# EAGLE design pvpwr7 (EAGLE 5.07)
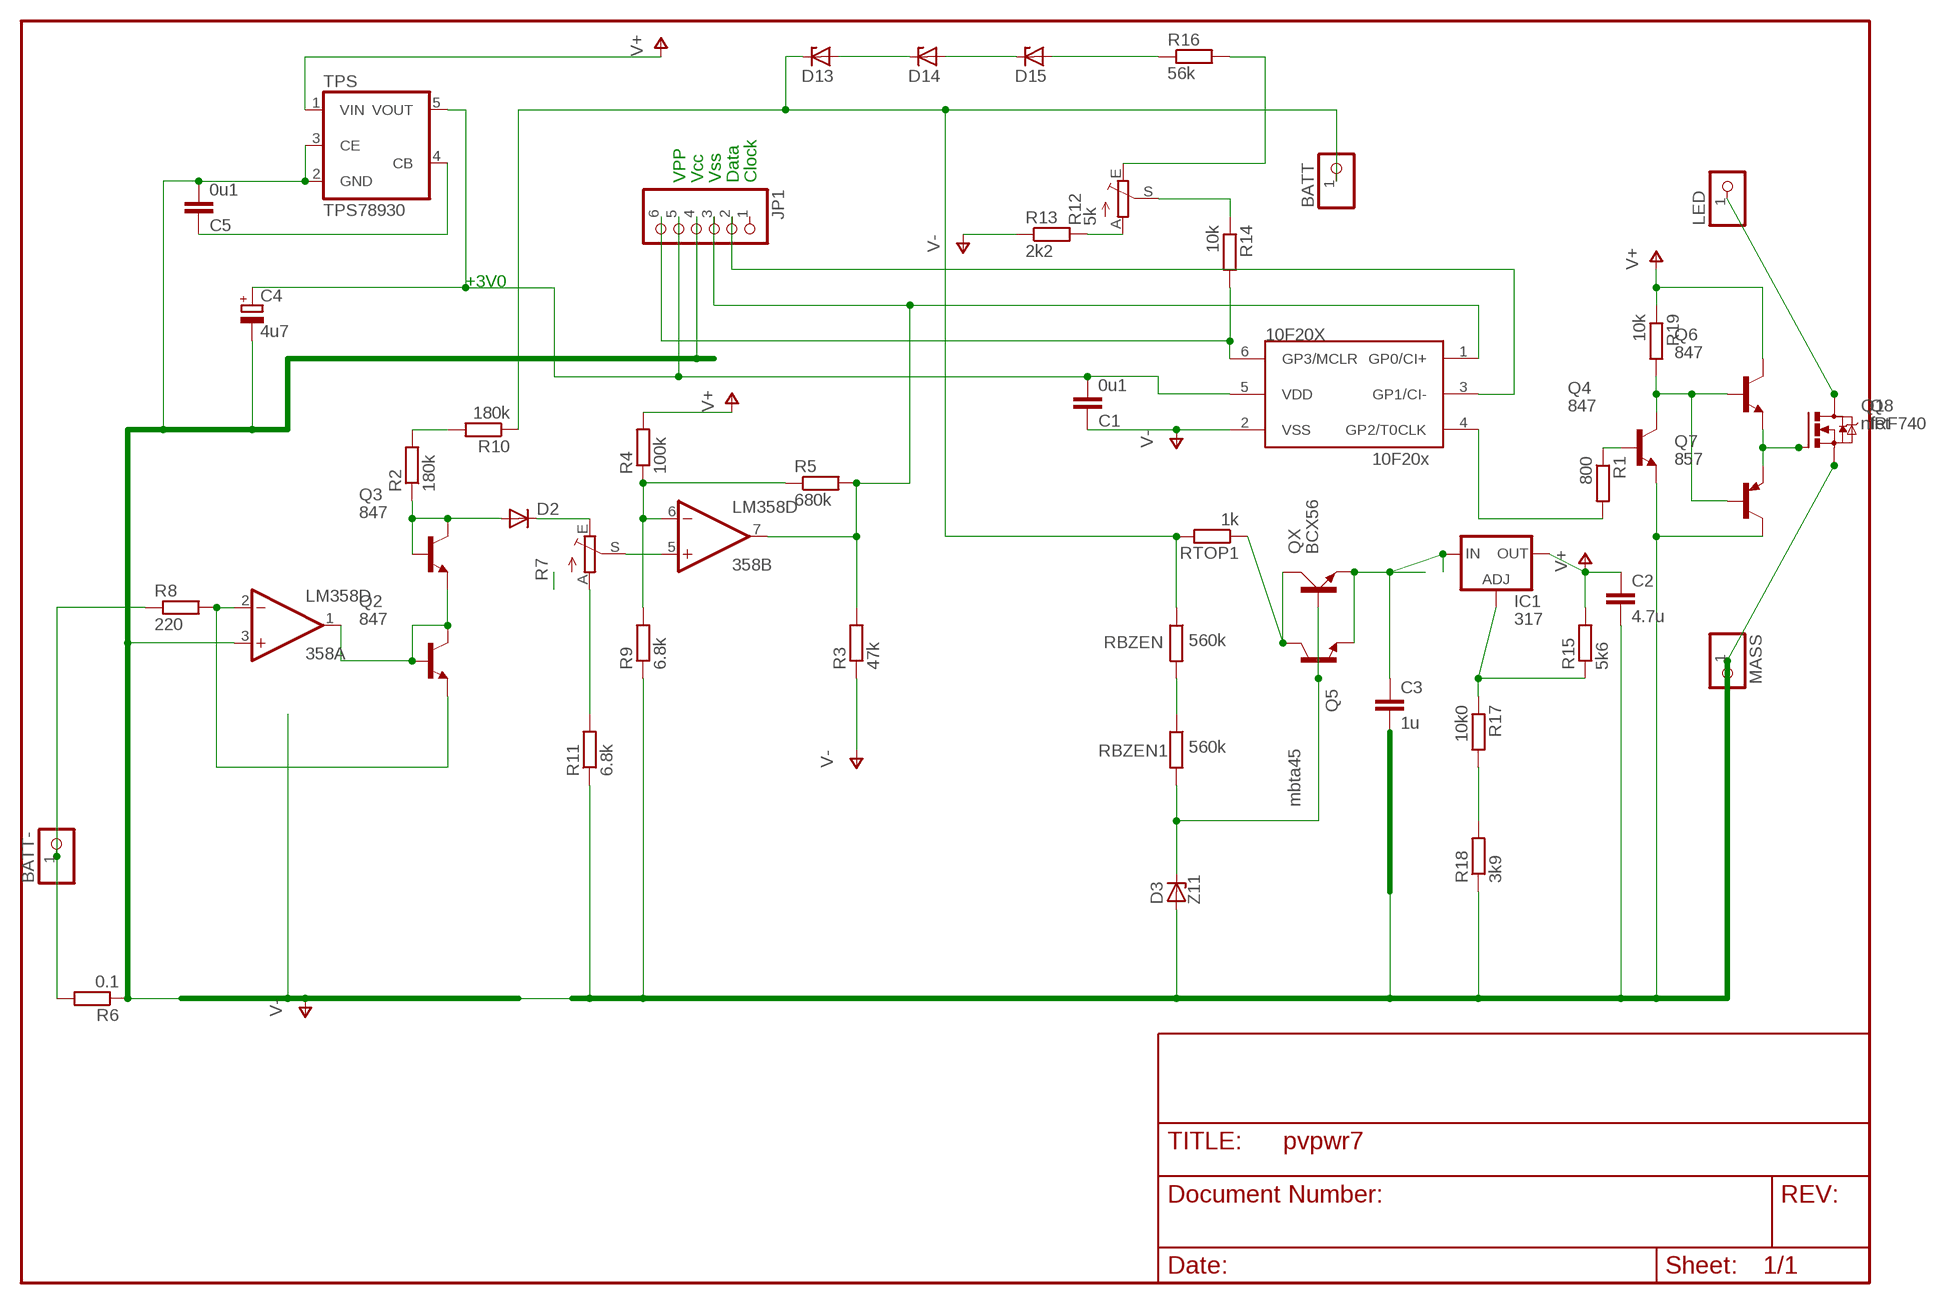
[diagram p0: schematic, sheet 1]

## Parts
10F20X  10F20x  PIC10F204OT  [SOT23-6]
358  LM358D  [SO08]
BATT  PINHD-1X1  [1X01]
BATT-  PINHD-1X1  [1X01]
C1  0u1  C-EUC1206  [C1206]
C2  4.7u  C-EUC1206  [C1206]
C3  1u  C-EUC1206  [C1206]
C4  4u7  CPOL-EUSMCA  [SMC_A]
C5  0u1  C-EUC0805  [C0805]
D2  DIODE-SOD80C  [SOD80C]
D3  Z11  ZENER-DIODESOD80C  [SOD80C]
D13  ZENER-DIODESOD80C  [SOD80C]
D14  ZENER-DIODESOD80C  [SOD80C]
D15  ZENER-DIODESOD80C  [SOD80C]
IC1  317  LM317D_PAKMABDT  [DPACK]
JP1  PINHD-1X6  [1X06BOX]
LED  PINHD-1X1  [1X01]
MASS  PINHD-1X1  [1X01]
Q1  nfet  N-HEXFET_DPAK-  [TO252]
Q2  847  BC847ALT1SMD  [SOT23]
Q3  847  BC847ALT1SMD  [SOT23]
Q4  847  BC847ALT1SMD  [SOT23]
Q5  mbta45  BC847ALT1SMD  [SOT23]
Q6  847  BC847ALT1SMD  [SOT23]
Q7  857  BC857ALT1SMD  [SOT23-BEC]
Q8  IRF740  [TO220BV]
QX  BCX56  [SOT223]
R1  800  R-EU_R0805  [R0805]
R2  180k  R-EU_R1206  [R1206]
R3  47k  R-EU_R0805  [R0805]
R4  100k  R-EU_R0805  [R0805]
R5  680k  R-EU_R1206  [R1206]
R6  0.1  R-EU_R2512  [R2512]
R7  TRIM_EU-S64W  [S64W]
R8  220  R-EU_R0805  [R0805]
R9  6.8k  R-EU_R0805  [R0805]
R10  180k  R-EU_R1206  [R1206]
R11  6.8k  R-EU_R0805  [R0805]
R12  5k  TRIM_EU-S64W  [S64W]
R13  2k2  R-EU_R0805  [R0805]
R14  10k  R-EU_R0805  [R0805]
R15  5k6  R-EU_R0805  [R0805]
R16  56k  R-EU_R0805  [R0805]
R17  10k0  R-EU_R0805  [R0805]
R18  3k9  R-EU_R0805  [R0805]
R19  10k  R-EU_R0805  [R0805]
RBZEN  560k  R-EU_R1206  [R1206]
RBZEN1  560k  R-EU_R1206  [R1206]
RTOP1  1k  R-EU_R1206  [R1206]
TPS  TPS78930  TPS78930SOT23-5  [SOT25]

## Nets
C: Q5.3(C) QX.2(C) RTOP1.1
CB: D3.C Q5.1(B) QX.1(B) RBZEN1.2
GND1: IC1.1(ADJ) R15.1 R17.1
HOT: LED.1 Q1.3(D) Q8.D
N$1: Q4.1(B) R1.1
N$2: R7.A R11.2
N$3: BATT-.1 R6.2 R8.1
N$4: 10F20X.1(GP0/CI+) 358.7(B:OUT) JP1.3 R3.2 R5.2
N$5: 10F20X.4(GP2/T0CLK) R1.2
N$6: R2.2 R10.2
N$7: 358.1(A:OUT) Q2.1(B) Q2.3(C) Q3.2(E)
N$8: 10F20X.3(GP1/CI-) JP1.2
N$9: 10F20X.5(VDD) C1.2 C4.+ JP1.5 TPS.5(VOUT)
N$10: 358.2(A:-IN) Q2.2(E) R8.2
N$11: C5.1 TPS.4(CB)
N$12: D2.A Q3.1(B) Q3.3(C) R2.1
N$13: D2.C R7.E
N$15: 358.5(B:+IN) R7.S
N$17: 358.6(B:-IN) R4.1 R5.1 R9.2
N$18: D15.A R16.1
N$19: RBZEN1.1 RBZEN.2
N$20: C3.1 IC1.3(IN) Q5.2(E) QX.3(E)
N$21: Q4.3(C) Q6.1(B) Q7.B R19.2
N$23: D14.A D15.C
N$24: D13.A D14.C
N$25: R12.E R16.2
N$26: R12.A R13.2
N$27: R12.S R14.1
N$28: R17.2 R18.2
N$31: Q1.1(G) Q6.2(E) Q7.E Q8.G
PIR: 10F20X.6(GP3/MCLR) JP1.6 R14.2
V+: C2.1 IC1.4(OUT) Q6.3(C) R4.2 R15.2 R19.1 TPS.1(VIN)
V-: 10F20X.2(VSS) 358.3(A:+IN) C1.1 C2.2 C3.2 C4.- C5.2 D3.A JP1.4 MASS.1 Q1.2(S) Q4.2(E) Q7.C Q8.S R3.1 R6.1 R9.1 R11.1 R13.1 R18.1 TPS.2(GND) TPS.3(CE)
VPLUS: BATT.1 D13.C R10.1 RBZEN.1 RTOP1.2
Unconnected: JP1.1

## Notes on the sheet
- VPP | Vcc | Vss | Data | Clock
- +3V0

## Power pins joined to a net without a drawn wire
V+: 358.8(P:V+)
V-: 358.4(P:V-)

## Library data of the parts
10F20X = microchip-3:PIC10F2*: uPC nW 0,25/0,5k Program Flash memory Comparator
358 = linear:LM358: OP AMP also LM158; LM258; LM2904 Source: http://cache.national.com/ds/LM/LM158.pdf
BATT BATT- LED MASS = pinhead:PINHD-1X1: PIN HEADER
C1-C3 C5 = rcl:C-EU: CAPACITOR, European symbol
C4 = rcl(2):CPOL-EU: POLARIZED CAPACITOR, European symbol
D2 = diode:DIODE-: DIODE
D3 D13-D15 = diode:ZENER-DIODE: Z-Diode
IC1 = v-reg:LM317?*: 500 mA Adjustable Output Positive Voltage Regulator Source: http://www.onsemi.co.jp .. LM317M-D.PDF
JP1 = pinhead:PINHD-1X6: PIN HEADER
Q1 = transistor-power:N-HEXFET_?-*: HEXFET® Power MOSFET
Q2-Q6 = transistor-npn:BC847*: NPN Transistor
Q7 = transistor-pnp:BC857*: PNP Transistror
Q8 = transistor-power:IRF740: N-CHANNEL MOS FET
QX = transistor-power:BCX56
R1-R6 R8-R11 R13-R19 RBZEN RBZEN1 RTOP1 = rcl:R-EU_: RESISTOR, European symbol
R7 R12 = pot:TRIM_EU-: POTENTIOMETER
TPS = v-reg:TPS78930

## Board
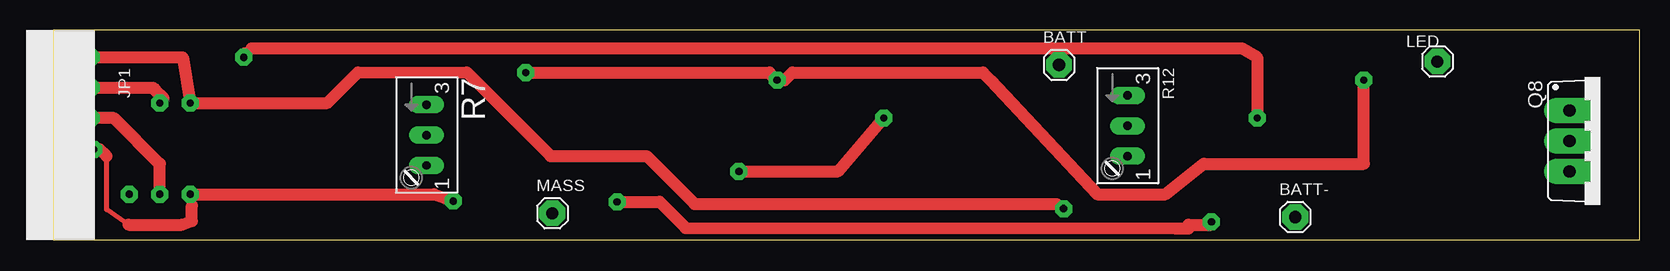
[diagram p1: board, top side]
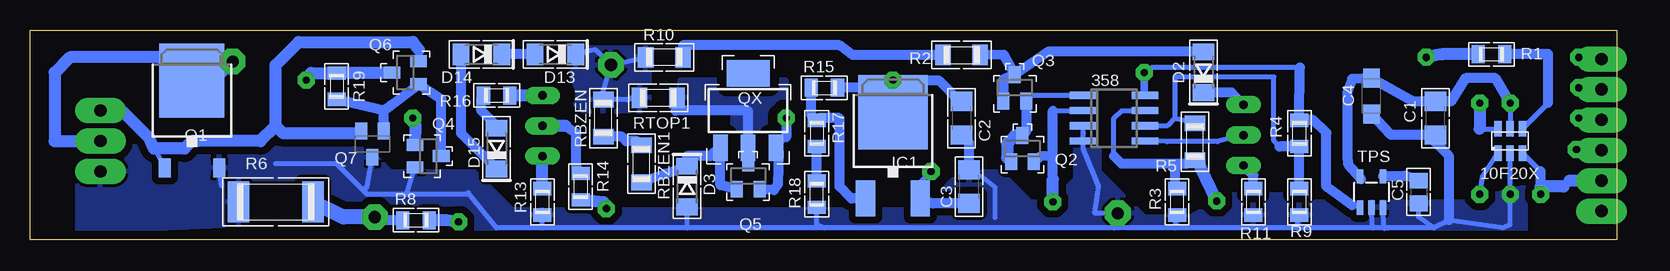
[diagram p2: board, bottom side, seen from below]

Size 132.24 x 17.5 mm. Coordinates in mm from the lower left corner, seen from the top.
Outline: 0,0 132.24,0 132.24,17.5 0,17.5 0,0
Copper layers (1*16): Top 0.035mm / dielectric 1.5mm / Bottom 0.035mm
Design rules "default *": minimum track width 10mil, minimum drill 24mil, track to track 8mil, track to pad 8mil, pad to pad 8mil, via to via 8mil, smd to smd 8mil, copper to edge 30mil, drill to drill 8mil, minimum pad ring 15mil, minimum via ring 8mil, stop-mask expansion 4mil, vias tented up to drill 0mil, thermal gap 10mil

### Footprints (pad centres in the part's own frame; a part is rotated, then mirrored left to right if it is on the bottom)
SOT23-6 = smd 0.635 x 1.27: 1 -1.016,-1.016; 2 0,-1.016; 3 1.016,-1.016; 4 1.016,1.016; 5 0,1.016; 6 -1.016,1.016
SO08 = smd 0.6 x 2.2: 1 -1.905,-2.6; 2 -0.635,-2.6; 3 0.635,-2.6; 4 1.905,-2.6; 5 1.905,2.6; 6 0.635,2.6; 7 -0.635,2.6; 8 -1.905,2.6
1X01 = drill 1.016 octagon: 1 0,0
C1206 = smd 1.6 x 1.8: 1 -1.4,0; 2 1.4,0
SMC_A = smd 1.6 x 1.4: + -1.5,0; - 1.5,0
C0805 = smd 1.3 x 1.5: 1 -0.95,0; 2 0.95,0
SOD80C = smd 1.4 x 1.8: A 1.7,0; C -1.7,0
DPACK = smd 1.6 x 3: 1 -2.28,-4.8; 3 2.28,-4.8 | smd 5.8 x 6.2: 4 0,2.38
1X06BOX = drill 1.016 long: 1 -6.35,0; 2 -3.81,0; 3 -1.27,0; 4 1.27,0; 5 3.81,0; 6 6.35,0
TO252 = smd 1 x 1.6: 1 -2.28,-3.53; 2 2.28,-3.53 | smd 5.4 x 6.2: 3 0,3.77
SOT23 = smd 1 x 1.4: 1 -0.95,-1.1; 2 0.95,-1.1; 3 0,1.1
SOT23-BEC = smd 1 x 1.4: B -0.95,-1.1; C 0,1.1; E 0.95,-1.1
TO220BV = drill 1.016 long: D 0,-2.54; G -2.54,-2.54; S 2.54,-2.54
SOT223 = smd 1.219 x 2.235: 1 -2.311,-3.099; 2 0,-3.099; 3 2.311,-3.099 | smd 3.6 x 2.2: 4 0,3.099
R0805 = smd 1.1 x 1.5: 1 -1.1,0; 2 1.1,0
R1206 = smd 1.3 x 1.7: 1 -1.55,0; 2 1.55,0
R2512 = smd 1.8 x 3.4: 1 -3.1,0; 2 3.1,0
S64W = drill 0.7 long: A 2.54,1.27; E -2.54,1.27; S 0,1.27
SOT25 = smd 0.55 x 1.2: 1 -0.95,-1.3; 2 0,-1.3; 3 0.95,-1.3; 4 0.95,1.3; 5 -0.95,1.3

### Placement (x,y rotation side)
10F20X  8.89,8.26 0 bottom
358  41.91,10.16 270 bottom
BATT  83.82,14.61 0 top
BATT-  103.5,1.91 0 top
C1  15.11,10.16 90 bottom
C2  54.61,10.16 270 bottom
C3  53.98,4.45 90 bottom
C4  20.45,12 270 bottom
C5  16.51,4 270 bottom
D2  34.45,14 90 bottom
D3  77.47,4.45 270 bottom
D13  88.46,15.5 180 bottom
D14  94.62,15.5 180 bottom
D15  93.34,7.62 90 bottom
IC1  60.33,8.26 0 bottom
JP1  1.27,8.75 90 top
LED  115.35,14.89 0 top
MASS  41.59,2.22 0 top
Q1  118.75,9.53 0 bottom
Q2  49.53,7.62 0 bottom
Q3  50.16,12.7 0 bottom
Q4  99.06,6.99 270 bottom
Q5  72.39,5.33 0 bottom
Q6  100.97,13.97 90 bottom
Q7  103.7,8 180 bottom
Q8  128.91,8.26 270 top
QX  72.39,10.79 0 bottom
R1  10.45,15.5 0 bottom
R2  54.61,15.43 180 bottom
R3  36.64,3.17 90 bottom
R4  26.45,8.89 90 bottom
R5  35.15,8.2 270 bottom
R6  111.76,3.17 0 bottom
R7  29.84,8.75 270 top
R8  100.08,1.65 0 bottom
R9  26.45,3.17 90 bottom
R10  79.38,15.24 0 bottom
R11  30.29,3.17 90 bottom
R12  88.26,9.53 270 top
R13  89.53,3.17 90 bottom
R14  86.36,4.45 270 bottom
R15  66.04,12.7 0 bottom
R16  93.34,12.06 0 bottom
R17  66.67,8.89 270 bottom
R18  66.67,3.81 90 bottom
R19  106.68,12.83 270 bottom
RBZEN  84.46,10.16 270 bottom
RBZEN1  81.28,6.35 270 bottom
RTOP1  79.88,11.87 180 bottom
TPS  20.45,4 0 bottom

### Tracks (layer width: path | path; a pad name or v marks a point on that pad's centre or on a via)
C
  Bottom 0.406: Q5.3 QX.2 | 78.46,10.79 RTOP1.1
  Bottom 0.813: QX.2 72.39,10.79 78.46,10.79
  pour Bottom (isolate 0.813): 69.85,13.34 78.1,13.34 78.1,10.79 73.66,10.79 73.66,8.26 69.22,8.26 69.22,13.34
CB
  Bottom 0.406: 77.47,6.99 D3.C | QX.1 74.78,7.62
  Bottom 0.813: QX.1 74.7,4.58 Q5.1 | 77.47,6.99 75.56,6.99 74.78,7.62 | D3.C 79.3,5.51 RBZEN1.2
GND1
  Bottom 0.406: 66.5,10.16 R17.1 67.14,10.46
  Bottom 0.813: IC1.1 63.78,3.46 64.77,4.45 64.77,10.16 66.5,10.16 | 67.14,10.46 R15.1
HOT
  Bottom 1.016: LED.1 116.94,13.29 Q1.3 119.38,13.29 121.32,15.24 128.91,15.24 130.18,13.97 130.18,8.26 Q8.D
N$1  (via drill 0.6 pad 1.42)
  Top 0.406: v15.88,15.24 15.88,15.88 16.51,16
  Top 1.016: 16.51,16 99.06,16 100.33,15.24 v100.33,10.16
  Bottom 0.406: v100.33,10.16 100.14,9.69
  Bottom 1.016: R1.1 14.53,15.49 v15.88,15.24 | 100.14,9.69 Q4.1
N$2
  Bottom 0.813: R11.2 30.29,5.38 R7.A
N$3
  Bottom 0.406: 103.25,1.65 BATT-.1
  Bottom 0.813: R8.1 103.25,1.65
  Bottom 1.27: BATT-.1 106.12,1.91 R6.2
N$4  (via drill 0.6 pad 1.42)
  Top 0.406: 4.45,6.99 4.45,2.54 6.29,1.27 | 11.56,2.86 v11.43,3.81
  Top 1.016: v33.34,3.24 31.75,3.81 v11.43,3.81 | 6.29,1.27 10.73,1.27 11.56,1.59 11.56,2.86 | v3.37,7.56 3.87,7.56 4.45,6.99
  Bottom 0.406: 10F20X.1 11.18,5.33 v11.43,3.81 | 358.7 41.27,10.79 41.91,10.16 41.91,6.99 | 36.83,4.85 R3.2 | R5.2 34.7,6.13 35.88,6.35
  Bottom 0.813: 41.91,6.99 41.27,6.35 36.83,6.35 | 35.88,6.35 36.83,6.35 | 36.83,6.35 36.83,4.85
  Bottom 1.016: v33.34,3.24 34.7,6.13 | JP1.3 3.29,7.48 v3.37,7.56
N$5
  Bottom 0.406: 10F20X.4 5.71,11.43
  Bottom 0.813: 5.71,11.43 5.71,15.51 R1.2
N$6
  Bottom 0.406: 77.82,16.25 R10.2
  Bottom 0.813: R2.2 63.69,15.43 64.77,16.25 77.82,16.25
N$7
  Bottom 0.406: 358.1 48.75,12.06 Q3.2 | 49.22,9.04 Q2.3
  Bottom 0.813: Q3.2 49.22,9.04
  Bottom 1.016: Q2.3 50.15,8.72 50.8,8.06 50.8,6.84 Q2.1
N$8  (via drill 0.6 pad 1.42)
  Bottom 0.406: 6.35,4.45 v6.35,3.81 | 6.35,5.71 10F20X.3 | 3.95,4.94 4.45,4.45
  Bottom 0.813: 6.35,4.45 6.35,5.71
  Bottom 1.016: JP1.2 3.95,4.94 | 4.45,4.45 6.35,4.45
N$9  (via drill 0.6 pad 1.42)
  Top 0.406: 9.2,11.83 9.2,11.74 v8.89,11.43
  Top 1.016: 9.2,11.83 8.47,12.56 8.33,12.7 v3.18,12.7
  Bottom 0.406: v8.89,11.43 10F20X.5 | 21.3,5.08 TPS.5
  Bottom 0.813: 21.3,5.08 22.42,6.35 22.45,7.05 22.45,12.32 22.06,13.44 C4.+ 16.98,11.53 C1.2 13.84,11.56 12.64,13.5 10.1,13.5 v8.89,11.43
  Bottom 1.016: JP1.5 3.04,12.56 v3.18,12.7
N$10  (via drill 0.6 pad 1.42)
  Top 0.406: 94.62,0.95 94.62,1.27 | 96.52,1.27 v96.52,1.5
  Top 1.016: 94.62,0.95 93.54,0.95 52.7,1 50.55,3.17 v46.99,3.17 | 94.62,1.27 96.52,1.27
  Bottom 0.406: 46.99,10.79 358.2
  Bottom 0.813: 46.99,6.99 46.99,10.79 | 46.99,5.08 46.99,6.99 | Q2.2 48.01,6.98 46.99,6.99
  Bottom 1.016: R8.2 97.54,1.65 v96.52,1.5 | v46.99,3.17 46.99,5.08
N$11
  Bottom 0.813: C5.1 17.69,5.36 17.75,5.3 TPS.4
N$12
  Bottom 0.406: 47.28,15.7 47.33,15.75
  Bottom 0.813: 47.33,15.75 Q3.3 | Q3.1 51.12,13.42 Q3.3 | R2.1 51.08,15.44 Q3.3 | D2.A 47.28,15.7
N$13
  Bottom 0.406: R7.E 31.9,12.08
  Bottom 0.813: D2.C 32.12,12.3 R7.E
N$15
  Bottom 0.406: R7.S 33.29,8.2 37.47,8.2 358.5
N$17
  Bottom 0.406: 358.6 37.47,9.53 36.83,10.16 | 36.83,10.16 35.9,9.97 R5.1 | 28.11,7.79 28.57,8.26 28.57,13.6 36.83,13.6 36.83,10.16
  Bottom 0.813: 28.11,7.79 R4.1 R9.2
N$18
  Bottom 0.406: D15.A 93.34,9.53 | 94.62,11.89 R16.1
  Bottom 0.813: 93.34,9.53 94.62,10.79 94.62,11.89
N$19
  Bottom 0.406: RBZEN1.1 81.63,8.26
  Bottom 0.813: RBZEN.2 82.91,8.61 82.55,8.26 81.63,8.26
N$20  (via drill 0.6 pad 1.42)
  Top 1.016: v57.15,5.71 65.41,5.71 v69.22,10.16
  Bottom 0.406: 69.85,7.47 QX.3 69.22,8.56 | IC1.3 58.05,4.82 v57.15,5.71
  Bottom 0.813: C3.1 57,3.04 IC1.3 | Q5.2 70.25,4.17 69.91,4.64 69.85,7.47 | v69.22,10.16 69.22,8.56
N$21
  Bottom 0.406: Q7.B 102.75,10.78 | Q6.1 100.19,12.7
  Bottom 0.813: Q4.3 97.96,11.75 Q6.1 | 102.75,10.78 R19.2 | Q7.B 102.81,10.73 102.04,11.3 100.19,12.7
N$23
  Bottom 0.813: D14.A 96.31,8.89 D15.C
N$24
  Bottom 0.406: D13.A 90.81,15.5
  Bottom 0.813: 90.81,15.5 D14.C
N$25
  Bottom 1.016: R12.E R16.2
N$26
  Bottom 1.016: R13.2 R12.A
N$27
  Bottom 0.406: R14.1 86.69,6.18
  Bottom 0.813: 87.63,9.53 86.69,8.89 86.69,6.18
  Bottom 1.016: 87.63,9.53 R12.S
N$28
  Bottom 0.813: R18.2 R17.2
N$31
  Bottom 0.406: 99.82,15.87 Q6.2 | Q7.E 105.26,8.89 | 122.29,8.52 Q1.1
  Bottom 1.016: 99.82,15.87 100.33,16.51 109.85,16.51 111.76,14.61 111.76,9.53 | 111.76,9.53 111.12,8.89 105.26,8.89 | 111.76,9.53 113.03,8.26 118.75,8.26 119.38,7.62 121.92,7.62 122.29,8.52 124.57,10.79 Q8.G
PIR  (via drill 0.6 pad 1.42)
  Top 0.406: 83.63,3 v84.2,2.6
  Top 1.016: 83.63,3 53.45,3 49.45,7 41.45,7 34.45,14 25.4,13.97 22.86,11.43 v11.43,11.43 10.79,15.24 v3.18,15.24
  Bottom 0.406: 11.43,9.27 10F20X.6 | v84.2,2.6 84.46,3.13
  Bottom 1.016: 84.46,3.13 R14.2 | v11.43,11.43 11.43,9.27 | JP1.6 3.04,15.1 v3.18,15.24
V+  (via drill 0.6 pad 1.42)
  Top 0.406: v60.33,13.34 60.96,13.34
  Top 1.016: v109.22,13.34 109.22,6.35 95.88,6.35 92.71,3.81 87,3.81 78.1,13.34 77.47,13.97 61.59,13.97 60.96,13.34 | v39.37,13.97 59.69,13.97 v60.33,13.34
  Bottom 0.406: 60.72,11.03 IC1.4 | 60.72,11.03 62.39,12.7 | TPS.1 22.06,2.89 | v60.33,13.34 60.33,11.43 60.72,11.03 | R19.1 105.81,13.97 | 26.42,14.4 38.73,14.4 v39.37,13.97 | 39.37,12.12 358.8 | 54.74,11.56 C2.1
  Bottom 0.61: v39.37,13.97 39.37,12.12
  Bottom 0.813: 62.39,12.7 R15.2 | 22.06,2.89 24.2,4.45 24.2,8.95 25.29,9.99 R4.2 26.42,14.4 | 54.74,11.56 56.52,13.34 v60.33,13.34
  Bottom 1.016: R19.1 108.82,13.93 v109.22,13.34 | 105.81,13.97 Q6.3
V-  (via drill 0.6 pad 1.42)
  Top 1.016: v8.89,3.81 8.89,6.35 5.08,10.16 v3.18,10.16
  Bottom 0.406: C5.2 16.51,1.91 15.24,1 | 15.24,1 13.97,1.64 9.53,1 8.89,1.27 v8.89,3.81 10F20X.2 | 15.11,8.12 C1.1 | 15.24,1 19.05,1 | 19.05,1 20.32,1 | TPS.3 19.37,0.95 19.05,1 | 20.32,1 TPS.2 | 44.45,7.62 43.18,4.45 43.5,2.22 MASS.1 41.59,1.32 41.91,1 | 44.45,7.62 358.4 | 358.3 44.45,8.89 44.45,7.62 | C3.2 52.84,5.21 51.82,4.38 51.82,1.84 | 20.32,1 26.67,1 | 26.67,1 36.83,1 | 36.83,1 41.91,1 | 53.98,8.12 C2.2 | R18.1 66.67,1.27 66.04,1 | 41.91,1 66.04,1 | 77.47,1 D3.A | 66.04,1 77.47,1 | 77.47,1 89.53,1 | 89.53,1 93.34,1 95.71,3.94 95.83,3.81 100.97,3.81 | 111.76,6.35 106.68,6.35 104.46,4.13 | 100.97,3.81 104.14,3.81 104.46,4.13 | 116.26,4.52 Q1.2 | R3.1 36.77,2.08 36.77,1.06 36.83,1 | 26.67,1 R9.1 | Q4.2 100.79,3.98 100.97,3.81 | Q7.C 104.14,4.45 104.46,4.13 | 89.53,1 R13.1
  Bottom 0.813: 15.11,8.12 13.97,6.99 13.97,1.64 | C1.1 18.84,8.77 C4.- | C3.2 53.98,8.12
  Bottom 1.016: JP1.4 3.04,10.02 v3.18,10.16
  pour Bottom (isolate 0.61): 7.62,4.45 7.62,0.64 95.88,0.64 97.16,1.91 105.41,1.91 108.59,5.08 114.3,5.08 114.3,1.27 128.27,0.64 128.27,6.99 119.38,8.89 105.41,8.89 102.24,5.71 95.25,5.71 92.07,2.54 57.79,2.54 54.61,5.71 51.44,5.71 48.9,3.17 46.99,3.17 45.09,5.08 45.09,8.26 45.72,8.89 44.45,8.89 43.18,7.62 43.18,5.71 39.37,1.91 35.56,1.91 32.39,3.81 26.67,3.81 26.67,3.17 10.79,3.17 10.16,3.81
VPLUS
  Bottom 0.406: D13.C 85.09,15.88 BATT.1 | BATT.1 84.46,12.35 RBZEN.1 82.47,11.71 RTOP1.2 | BATT.1 R10.1
  pour Bottom (isolate 1.27): 80.65,17.14 86.36,17.14 87,15.88 87,11.43 86.36,10.79 81.28,10.79 80.65,11.43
